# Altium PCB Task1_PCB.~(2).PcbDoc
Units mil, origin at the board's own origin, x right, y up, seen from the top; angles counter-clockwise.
Board outline 6000 x 4000 mil, 2 copper layers (Top Layer, Bottom Layer); 15 components, 13 nets, 94 pads, 0 vias.
Unrouted connection lines stored in the file: 44.
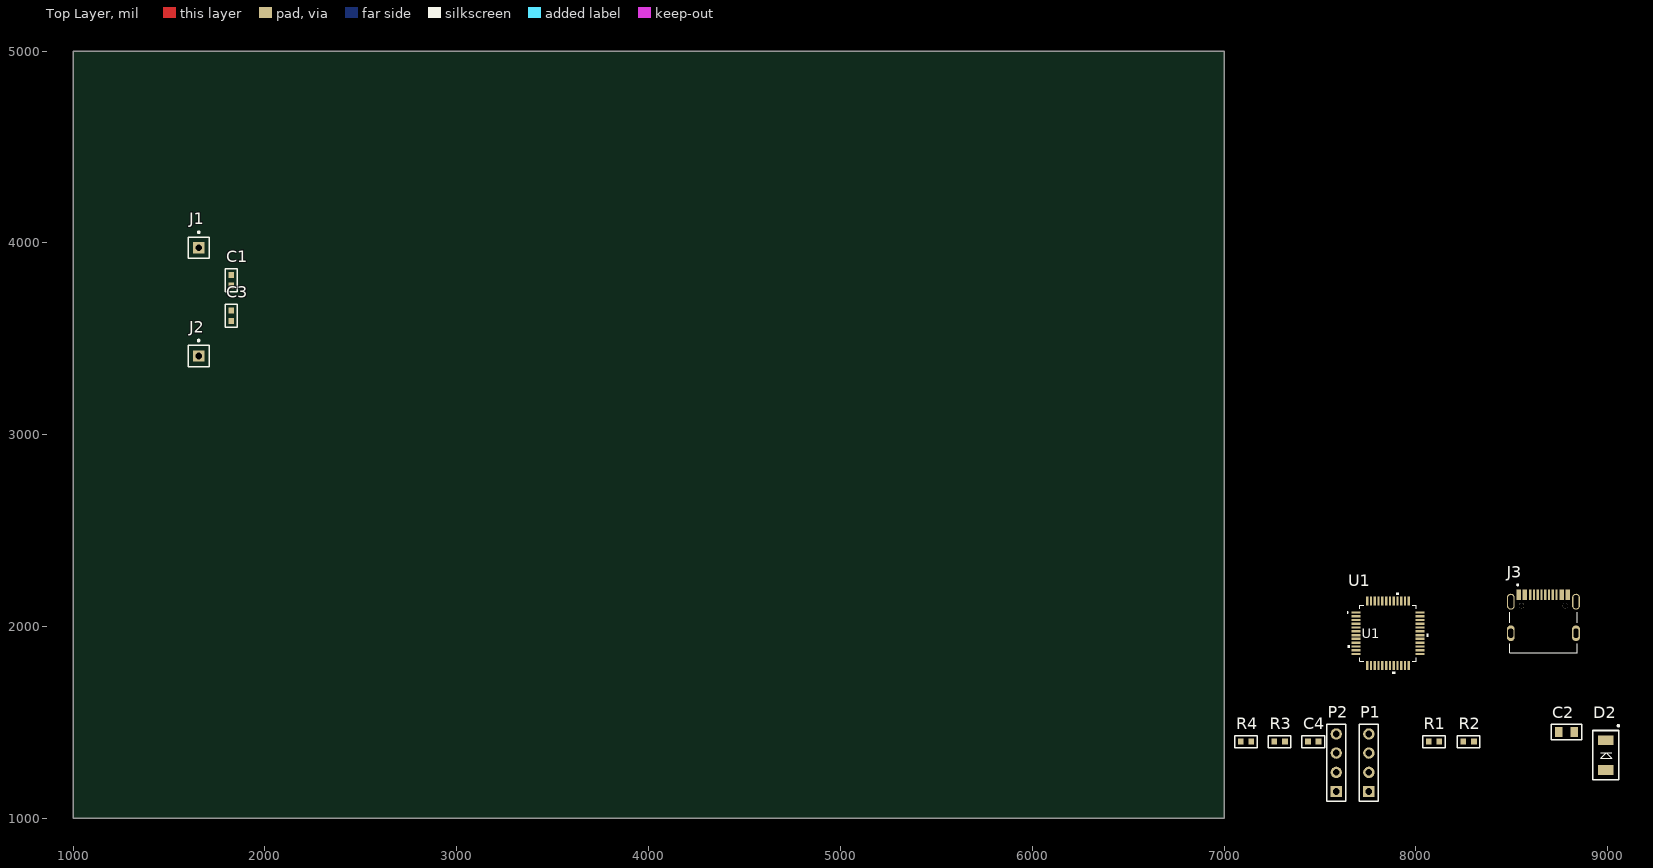
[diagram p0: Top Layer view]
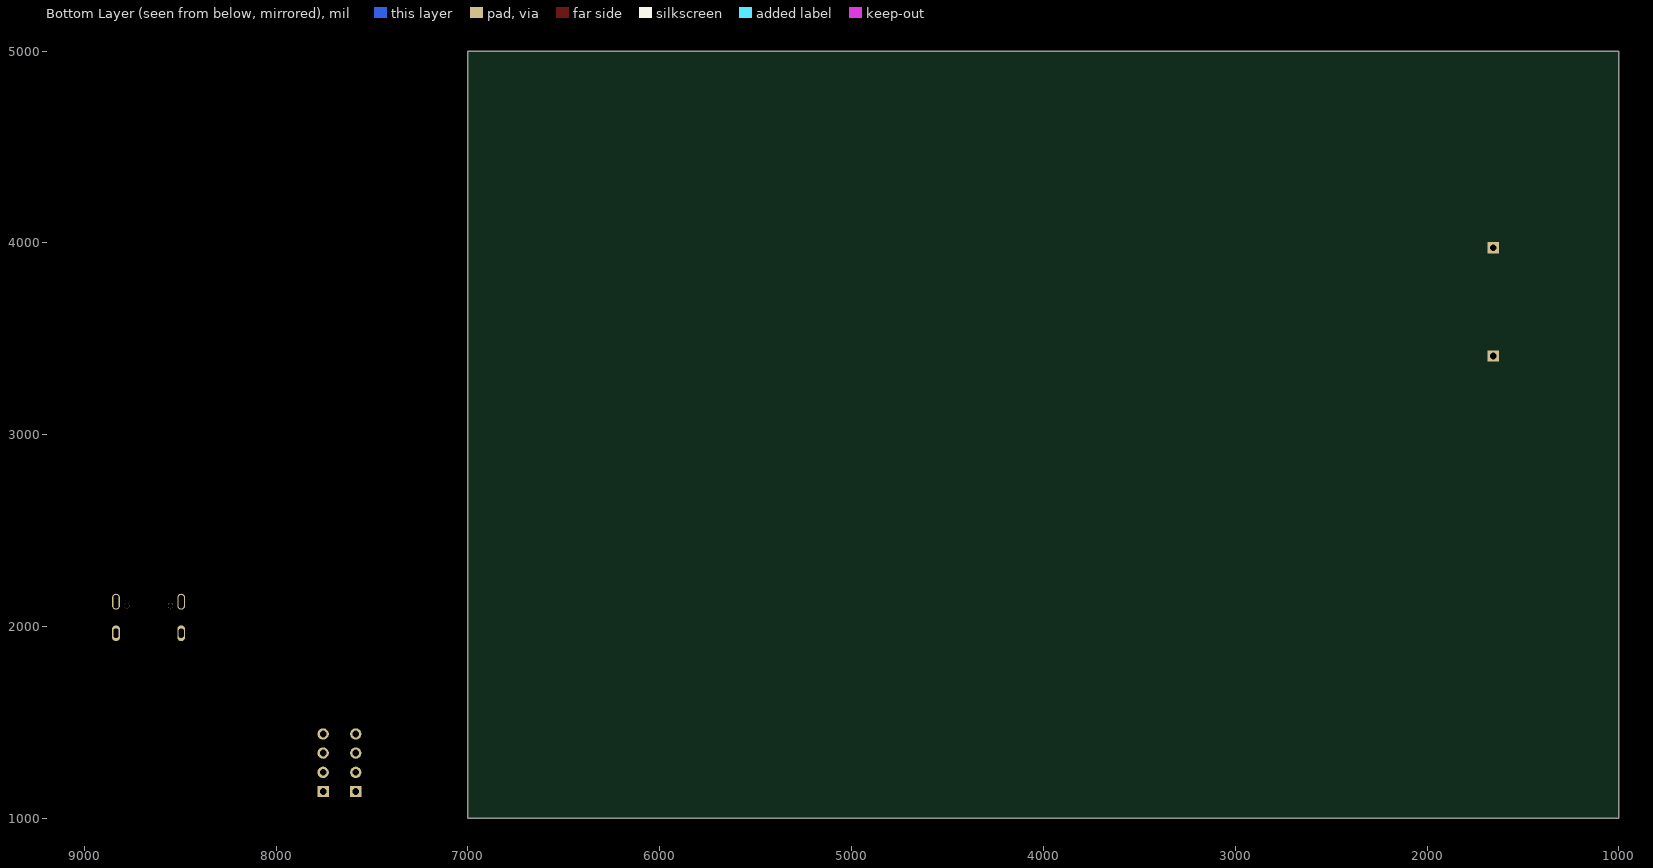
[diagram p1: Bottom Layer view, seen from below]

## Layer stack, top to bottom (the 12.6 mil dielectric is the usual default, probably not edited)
Top Solder: solder mask 0.4, Solder Resist, Dk 3.5
Top Layer: signal copper 1.4
Dielectric 1: dielectric 12.6, FR-4, Dk 4.8
Bottom Layer: signal copper 1.4
Bottom Solder: solder mask 0.4, Solder Resist, Dk 3.5

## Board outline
1000,1000 7000,1000 7000,5000 1000,5000

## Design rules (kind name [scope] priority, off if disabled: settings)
Clearance [All] p1: gap=10 ignorepadtopadclearanceinfootprint=TRUE
PolygonConnect [All] p1: connectstyle=Relief reliefconductorwidth=10 reliefentries=4 polygonreliefangle="90 Angle" airgapwidth=10
RoutingVias [All] p1: holewidth=28 width=50 viastyle="Through Hole" minholewidth=28 minwidth=50 maxholewidth=28 maxwidth=50
SolderMaskExpansion [All] p1: expansion=4 istentingtop=FALSE
SupplyNets "Schematic Supply Nets" [InNet('GND')] p1: voltage=0.000
Width [All] p1: maxlimit=10 minlimit=10 preferedwidth=10
30 further rules are at their usual default settings.

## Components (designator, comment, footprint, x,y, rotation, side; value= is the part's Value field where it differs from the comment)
C1 "100nF/50V/0603" C0603 1825,3805 r90 top
C2 "0805" C0805 8785,1450 r0 top
C3 "100nF/50V/0603" C0603 1825,3620 r90 top
C4 "0603" C0603 7465,1400 r0 top
D2 "SMBJ18CA-Q" SMBJ18CA-Q 8990,1330 r90 top
J1 "Socket" PIN1 1655,3975 r0 top
J2 "Socket" PIN1 1655,3410 r0 top
J3 "USB-C" HRO_TYPE-C-31-M-12 8664.92,1965 r0 top
P1 "Header 4" HDR1X4 7755,1140 r90 top
P2 "Header 4" HDR1X4 7585,1140 r90 top
R1 "0603" R0603 8095,1400 r0 top
R2 "0603" R0603 8275,1400 r0 top
R3 "0603" R0603 7290,1400 r0 top
R4 "0603" R0603 7115,1400 r0 top
U1 "STM32G431CBT6" LQFP48-7x7mm 7855,1965 r0 top

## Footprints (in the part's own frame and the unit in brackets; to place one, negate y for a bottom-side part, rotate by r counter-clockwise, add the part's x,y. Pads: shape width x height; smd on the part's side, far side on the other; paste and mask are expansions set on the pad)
C0603 [mil]
  rect 30x30 smd: 1(-27.5,0) 2(27.5,0)
  silkscreen extent -59,-31 59,31, body extent -32,-15 32,15, height 19
C0805 [mil]
  rect 40x50 smd: 1(-40,0) 2(40,0)
  silkscreen extent -79,-39 79,39, body extent -41,-25 40,25, height 26
HDR1X4 [mm] "Connector; Header; 4 Position"
  rect 1.5x1.5 hole 0.9: 1(0,0)
  round 1.5 hole 0.9: 2(2.54,0) 3(5.08,0) 4(7.62,0)
  silkscreen extent -1.27,-1.27 8.89,1.27
HRO_TYPE-C-31-M-12 [mm]
  rect 0.6x1.45 smd paste+0 mask+0.102: A1B12(-3.25,5.095) A4B9(-2.45,5.095) B1A12(3.25,5.095) B4A9(2.45,5.095)
  rect 0.3x1.45 smd paste+0 mask+0.102: A5(-1.25,5.095) A6(-0.25,5.095) A7(0.25,5.095) A8(1.25,5.095) B5(1.75,5.095) B6(0.75,5.095) B7(-0.75,5.095) B8(-1.75,5.095)
  oval 1.05x2.1 hole 0.65 slot 1.75 at 90 deg mask+0.102: S1(-4.32,4.18) S2(4.32,4.18)
  oval 1.05x2.1 hole 0.65 slot 1.25 at 90 deg mask+0.102: S3(-4.32,0) S4(4.32,0)
  round 0.7 hole 0.7 unplated mask+0: ""(-2.89,3.65) ""(2.89,3.65)
  silkscreen extent -4.47,-2.6 4.47,6.5
LQFP48-7x7mm [mil]
  rect 47x12 smd paste+0 mask+0: 1(-167.32,108.27) 2(-167.32,88.58) 3(-167.32,68.9) 4(-167.32,49.21) 5(-167.32,29.53) 6(-167.32,9.84) 7(-167.32,-9.84) 8(-167.32,-29.53) 9(-167.32,-49.21) 10(-167.32,-68.9) 11(-167.32,-88.58) 12(-167.32,-108.27) 25(167.32,-108.27) 26(167.32,-88.58) 27(167.32,-68.9) 28(167.32,-49.21) 29(167.32,-29.53) 30(167.32,-9.84) 31(167.32,9.84) 32(167.32,29.53) 33(167.32,49.21) 34(167.32,68.9) 35(167.32,88.58) 36(167.32,108.27)
  rect 12x47 smd paste+0 mask+0: 13(-108.27,-167.32) 14(-88.58,-167.32) 15(-68.9,-167.32) 16(-49.21,-167.32) 17(-29.53,-167.32) 18(-9.84,-167.32) 19(9.84,-167.32) 20(29.53,-167.32) 21(49.21,-167.32) 22(68.9,-167.32) 23(88.58,-167.32) 24(108.27,-167.32) 37(108.27,167.32) 38(88.58,167.32) 39(68.9,167.32) 40(49.21,167.32) 41(29.53,167.32) 42(9.84,167.32) 43(-9.84,167.32) 44(-29.53,167.32) 45(-49.21,167.32) 46(-68.9,167.32) 47(-88.58,167.32) 48(-108.27,167.32)
  silkscreen extent -214,-211 211,211, body extent -177,-177 177,177, height 63
PIN1 [mm] "Connector; Plug"
  rect 1.5x1.5 hole 0.9: 1(0,0)
  silkscreen extent -1.4,-1.4 1.4,2.17
R0603 [mil]
  rect 30x30 smd: 1(-27.5,0) 2(27.5,0)
  silkscreen extent -59,-31 59,31, body extent -32,-15 32,15, height 19
SMBJ18CA-Q [mm]
  rect 1.27x2.1 smd: A(-1.98,0) K(1.98,0)
  silkscreen extent -3.25,-1.75 3.97,1.75, body extent -2.68,-1.81 2.68,1.81, height 2.65

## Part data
C1 C3 C4: library part C0603
C2: library part C0805
J3: "USB-C (USB TYPE-C) USB 3.2 Gen 2 (USB 3.1 Gen 2, Superspeed + (USB 3.1)) Receptacle Connector 24 Position Surface Mount, Through Hole", Package=None
P1 P2: "Header, 4-Pin"
R1 R2 R3 R4: library part R0603
U1: "Mainstream Arm Cortex-M4 MCU 170 MHz with 128 Kbytes of Flash memory, Math Accelerator, Medium Analog level integration", Manufacturer_Name=STMicroelectronics

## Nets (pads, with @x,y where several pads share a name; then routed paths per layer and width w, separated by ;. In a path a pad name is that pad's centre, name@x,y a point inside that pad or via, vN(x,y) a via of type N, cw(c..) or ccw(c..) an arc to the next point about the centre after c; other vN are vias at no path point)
3.3V: C4.2 P1.4 P2.3 R1.2 R2.2 U1.20 U1.21 U1.24 U1.36 U1.48
DN: J3.A7 J3.B7 U1.25
DP: J3.A6 U1.26
GND: C2.1 C3.1 C4.1 D2.A J2.1 J3.A1B12 J3.B1A12 J3.S1 J3.S2 J3.S3 J3.S4 P1.3 P2.4 R3.1 R4.1 U1.19 U1.23 U1.35 U1.47
NetC1_1: C1.1 C3.2
NetC1_2: C1.2 J1.1
NetJ3_A5: J3.A5 R3.2
NetJ3_B5: J3.B5 R4.2
SCL: P2.1 R2.1 U1.45
SDA: P2.2 R1.1 U1.46
SWCLK: P1.2 U1.38
SWDIO: P1.1 U1.37
Vin: C2.2 D2.K J3.A4B9 J3.B4A9 U1.1
pads on no net: J3. J3.A8 J3.B6 J3.B8 U1.2 U1.3 U1.4 U1.5 U1.6 U1.7 U1.8 U1.9 U1.10 U1.11 U1.12 U1.13 U1.14 U1.15 U1.16 U1.17 U1.18 U1.22 U1.27 U1.28 U1.29 U1.30 U1.31 U1.32 U1.33 U1.34 U1.39 U1.40 U1.41 U1.42 U1.43 U1.44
